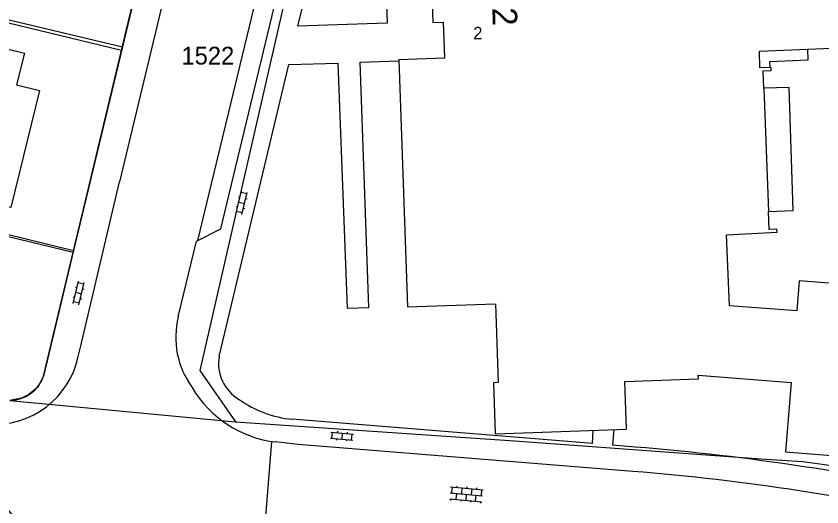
# Model space of a CAD drawing. Extents: x 148816 to 151297, y 399515 to 402500.
# Drawn here: x 150064.9 to 150146.7, y 400574.6 to 400624.4 of the extents above; entities that cross this region are included whole.
import ezdxf

# ---------------------------------------------------------------- set-up
doc = ezdxf.new("R2010")
doc.units = 0
for name, color, linetype in [('B01 Hoofdgebouw  [T] Norm', 7, 'Continuous'), ('B01 Hoofdgebouw secundair [T] Gem', 7, 'Continuous'), ('B01 hoofgebouw', 7, 'Continuous'), ('G01 perceelsgrens', 7, 'Continuous'), ('S02 Open verharding  Norm', 7, 'Continuous'), ('T04 Haag heg  [D] Gem', 7, 'Continuous'), ('V00 Kant verharding algemeen  [T] Norm', 7, 'Continuous'), ('V00 Kant verharding algemeen secundair  [T] Gem', 7, 'Continuous'), ('Z01 perceelnummer', 7, 'Continuous'), ('Z02 huisnummer', 7, 'Continuous'), ('Z02 Huisnummer  [Tekst] Norm', 7, 'Continuous')]:
    doc.layers.add(name, color=color, linetype=linetype)

msp = doc.modelspace()

# ---------------------------------------------------------------- linework, layer by layer
at = {"layer": 'B01 Hoofdgebouw  [T] Norm'}
for p, q in [((150060.92, 400621.79), (150065.78, 400620.6)), ((150065.78, 400620.6), (150064.99, 400617.4)), ((150064.99, 400617.4), (150067.33, 400616.83)), ((150067.33, 400616.83), (150064.42, 400604.96))]:
    msp.add_line(p, q, dxfattribs=at)
for points in [[(150106.53, 400642.882), (150107.221, 400623.701), (150108.25, 400623.738), (150108.381, 400620.086), (150103.754, 400619.92), (150104.653, 400594.879), (150113.55, 400595.208), (150113.849, 400587.209), (150113.349, 400587.192), (150113.52, 400582.03), (150126.86, 400582.49), (150126.69, 400587.33), (150134.14, 400587.59), (150134.13, 400587.97), (150143.55, 400587.22), (150142.99, 400580.19), (150163.74, 400578.55)], [(150165.125, 400595.898), (150144.382, 400597.541), (150144.14, 400594.481), (150137.292, 400595.002), (150136.994, 400602.174), (150142.131, 400602.456), (150142.114, 400602.761), (150141.321, 400602.742), (150141.252, 400604.561), (150143.768, 400604.647), (150143.342, 400617.132), (150140.778, 400617.044), (150140.711, 400618.809), (150141.537, 400618.846), (150141.525, 400619.152), (150140.376, 400619.108), (150140.344, 400620.807), (150194.611, 400623.071)]]:
    msp.add_lwpolyline(points, dxfattribs=at)
at = {"layer": 'B01 Hoofdgebouw secundair [T] Gem'}
msp.add_line((150140.778, 400617.044), (150141.252, 400604.561), dxfattribs=at)
at = {"layer": 'B01 hoofgebouw'}
for points in [[(150128.72, 400664.62), (150128.925, 400667.915), (150128.077, 400667.968), (150128.027, 400667.17), (150107.198, 400666.462), (150107.105, 400667.257), (150106.252, 400667.162), (150107.59, 400656.77), (150106.98, 400646.29), (150107.628, 400646.271), (150107.759, 400642.926), (150106.53, 400642.882), (150107.221, 400623.701), (150108.25, 400623.738), (150108.381, 400620.086), (150103.754, 400619.92), (150104.653, 400594.879), (150113.55, 400595.208), (150113.849, 400587.209), (150113.349, 400587.192), (150113.52, 400582.03)], [(150165.125, 400595.898), (150144.382, 400597.541), (150144.14, 400594.481), (150137.292, 400595.002), (150136.994, 400602.174), (150142.131, 400602.456), (150142.114, 400602.761), (150141.321, 400602.742), (150141.252, 400604.561), (150143.768, 400604.647), (150143.342, 400617.132), (150140.778, 400617.044), (150140.711, 400618.809), (150141.537, 400618.846), (150141.525, 400619.152), (150140.376, 400619.108), (150140.344, 400620.807), (150194.611, 400623.071)], [(150060.92, 400621.79), (150065.78, 400620.6), (150064.99, 400617.4), (150067.33, 400616.83), (150064.42, 400604.96), (150059.57, 400606.15)], [(150113.52, 400582.03), (150126.86, 400582.49), (150126.69, 400587.33), (150134.14, 400587.59), (150134.13, 400587.97), (150143.55, 400587.22), (150142.99, 400580.19), (150163.74, 400578.55)]]:
    msp.add_lwpolyline(points, dxfattribs=at)
at = {"layer": 'G01 perceelsgrens'}
for points in [[(150098.9, 400655.28), (150083.562, 400588.451), (150087.211, 400583.225)], [(150079.083, 400635.273), (150075.728, 400621.262)], [(150041.761, 400629.355), (150075.728, 400621.262)], [(150075.728, 400621.262), (150070.778, 400600.593)], [(150038.691, 400608.537), (150063.775, 400602.328), (150070.778, 400600.593)], [(150070.778, 400600.593), (150067.73, 400587.87), (150067.135, 400586.743), (150066.248, 400586.004), (150065.472, 400585.634), (150064.32, 400585.4)], [(150087.211, 400583.225), (150115.477, 400581.315), (150140.464, 400579.492), (150144.738, 400579.229), (150155.973, 400577.67), (150167.314, 400576.234), (150177.108, 400573.963), (150185.048, 400571.475), (150195.328, 400568.488), (150204.818, 400565.088), (150214.206, 400561.214), (150222.69, 400556.918), (150233.049, 400550.868), (150249.677, 400572.16), (150265.043, 400591.857)], [(150064.32, 400585.4), (150087.211, 400583.225)]]:
    msp.add_lwpolyline(points, dxfattribs=at)
at = {"layer": 'S02 Open verharding  Norm'}
for p, q in [((150087.266, 400604.394), (150087.792, 400606.633)), ((150088.342, 400606.35), (150087.758, 400606.487)), ((150087.85, 400604.257), (150088.376, 400606.496)), ((150087.497, 400606.035), (150087.643, 400606)), ((150088.227, 400605.863), (150088.373, 400605.829)), ((150087.269, 400605.061), (150087.415, 400605.027)), ((150087.529, 400605.514), (150088.113, 400605.376)), ((150087.999, 400604.89), (150088.145, 400604.855)), ((150087.884, 400604.403), (150087.3, 400604.54)), ((150070.729, 400595.241), (150071.255, 400597.48)), ((150070.96, 400596.882), (150071.106, 400596.847)), ((150071.805, 400597.197), (150071.221, 400597.334)), ((150071.313, 400595.104), (150071.839, 400597.343)), ((150071.69, 400596.71), (150071.836, 400596.676)), ((150070.732, 400595.908), (150070.878, 400595.874)), ((150070.992, 400596.361), (150071.576, 400596.223)), ((150071.347, 400595.25), (150070.763, 400595.387)), ((150071.462, 400595.737), (150071.608, 400595.702)), ((150096.875, 400582.189), (150099.166, 400581.978)), ((150096.97, 400581.578), (150097.025, 400582.175)), ((150097.536, 400582.279), (150097.523, 400582.13)), ((150098.02, 400582.084), (150097.966, 400581.486)), ((150098.532, 400582.187), (150098.518, 400582.038)), ((150098.961, 400581.395), (150099.016, 400581.992)), ((150096.82, 400581.592), (150099.111, 400581.381)), ((150097.468, 400581.532), (150097.454, 400581.383)), ((150098.463, 400581.44), (150098.45, 400581.291)), ((150109.018, 400576.633), (150112.305, 400576.334)), ((150109.168, 400576.62), (150109.113, 400576.022)), ((150109.666, 400576.574), (150109.679, 400576.724)), ((150110.164, 400576.529), (150110.109, 400575.931)), ((150110.661, 400576.484), (150110.675, 400576.633)), ((150111.159, 400576.438), (150111.105, 400575.841)), ((150111.657, 400576.393), (150111.671, 400576.542)), ((150112.155, 400576.347), (150112.101, 400575.75)), ((150108.909, 400575.438), (150112.196, 400575.139)), ((150108.964, 400576.036), (150112.25, 400575.736)), ((150109.059, 400575.425), (150109.045, 400575.275)), ((150109.611, 400575.977), (150109.557, 400575.379)), ((150110.607, 400575.886), (150110.553, 400575.288)), ((150111.548, 400575.198), (150111.603, 400575.795)), ((150110.055, 400575.334), (150110.041, 400575.185)), ((150111.05, 400575.243), (150111.037, 400575.094)), ((150112.046, 400575.152), (150112.033, 400575.003))]:
    msp.add_line(p, q, dxfattribs=at)
at = {"layer": 'T04 Haag heg  [D] Gem'}
for p, q in [((150041.529, 400629.112), (150075.644, 400620.916)), ((150038.65, 400608.191), (150070.739, 400600.435))]:
    msp.add_line(p, q, dxfattribs=at)
at = {"layer": 'V00 Kant verharding algemeen  [T] Norm'}
for p, q in [((150067.73, 400587.87), (150083.896, 400655.376)), ((150086.17, 400652.36), (150075.439, 400607.577)), ((150085.695, 400602.812), (150095.744, 400644.501)), ((150093.524, 400623.336), (150098.086, 400642.439)), ((150085.53, 400589.86), (150092.593, 400619.438)), ((150123.413, 400581.029), (150092.95, 400583.49)), ((150093.555, 400580.943), (150091.254, 400581.19)), ((150127.5, 400578.21), (150093.555, 400580.943)), ((150127.73, 400580.68), (150125.443, 400580.865))]:
    msp.add_line(p, q, dxfattribs=at)
for points in [[(150098.086, 400642.439), (150101.901, 400642.619), (150102.581, 400623.658), (150093.524, 400623.336)], [(150141.44, 400619.149), (150141.404, 400619.751), (150145.294, 400619.915), (150145.254, 400621.012)], [(150092.593, 400619.438), (150097.59, 400619.603), (150098.506, 400594.754), (150100.729, 400594.839), (150099.836, 400619.692), (150103.757, 400619.83)], [(150071.248, 400589.864), (150071.538, 400591.079), (150075.439, 400607.577)], [(150081.389, 400593.875), (150083.236, 400601.56), (150085.695, 400602.812)], [(150123.413, 400581.029), (150123.461, 400582.373)], [(150125.557, 400582.445), (150125.443, 400580.865)]]:
    msp.add_lwpolyline(points, dxfattribs=at)
for centre, radius, start, end in [((150089.709, 400591.791), 8.576, 165.93736, 216.30687), ((150062.737, 400591.676), 8.702, 266.75557, 347.97952), ((150089.761, 400589.174), 4.286, 170.78847, 239.25967), ((150064.246, 400589.091), 3.692, 271.14867, 340.68597), ((150092.579, 400592.455), 11.342, 210.41249, 263.29294), ((150094.068, 400594.734), 11.299, 234.89426, 264.32079), ((150107.786, 400334.973), 246.516, 77.34553, 85.3594), ((150107.554, 400333.567), 245.455, 77.39953, 85.33886), ((150058.631, 400569.481), 7.324, 342.57387, 74.54113)]:
    msp.add_arc(centre, radius, start, end, dxfattribs=at)
at = {"layer": 'V00 Kant verharding algemeen secundair  [T] Gem'}
for p, q in [((150093.8, 400644.97), (150083.352, 400601.619)), ((150090.852, 400581.233), (150090.231, 400573.646))]:
    msp.add_line(p, q, dxfattribs=at)

# ---------------------------------------------------------------- texts
at = {"layer": 'Z01 perceelnummer'}
msp.add_text('1522', height=1.8, dxfattribs=at).set_placement((150081.713, 400619.45))
at = {"layer": 'Z02 huisnummer'}
msp.add_text('2', height=2.5, rotation=272.00654, dxfattribs=at).set_placement((150113.237, 400625.196))
at = {"layer": 'Z02 Huisnummer  [Tekst] Norm'}
msp.add_text('2', height=1.25, dxfattribs=at).set_placement((150111.314, 400622.02))

doc.saveas('drawing.dxf')
